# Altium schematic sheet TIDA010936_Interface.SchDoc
size 431 x 279 mm; Date: Not shown in title block; ApprovedBy: Not shown in title block; CheckedBy: Not shown in title block; Author: Not shown in title block; CompanyName: Not shown in title block; Engineer: Not shown in title block; Organization: Not shown in title block; Address1: Not shown in title block; Address2: Not shown in title block; Address3: Not shown in title block; Address4: Not shown in title block; DocumentNumber: 2; Revision: Use project parameter SCH_Rev; SheetNumber: 2; SheetTotal: 3; PageSetup: Record=PageOptions¦CenterHorizontal=True¦CenterVertical=True¦PrintScale=1.00¦XCorrection=1.00¦YCorrection=1.00¦PrintKind=0¦BorderSize=5000000¦LeftOffset=0¦BottomOffset=0¦Orientation=2¦PaperLength=1000¦PaperWidth=1000¦Scale=100¦PaperSource=15¦PrintQuality=600¦MediaType=1¦DitherType=10¦PaperKind=Letter¦PrintScaleMode=1
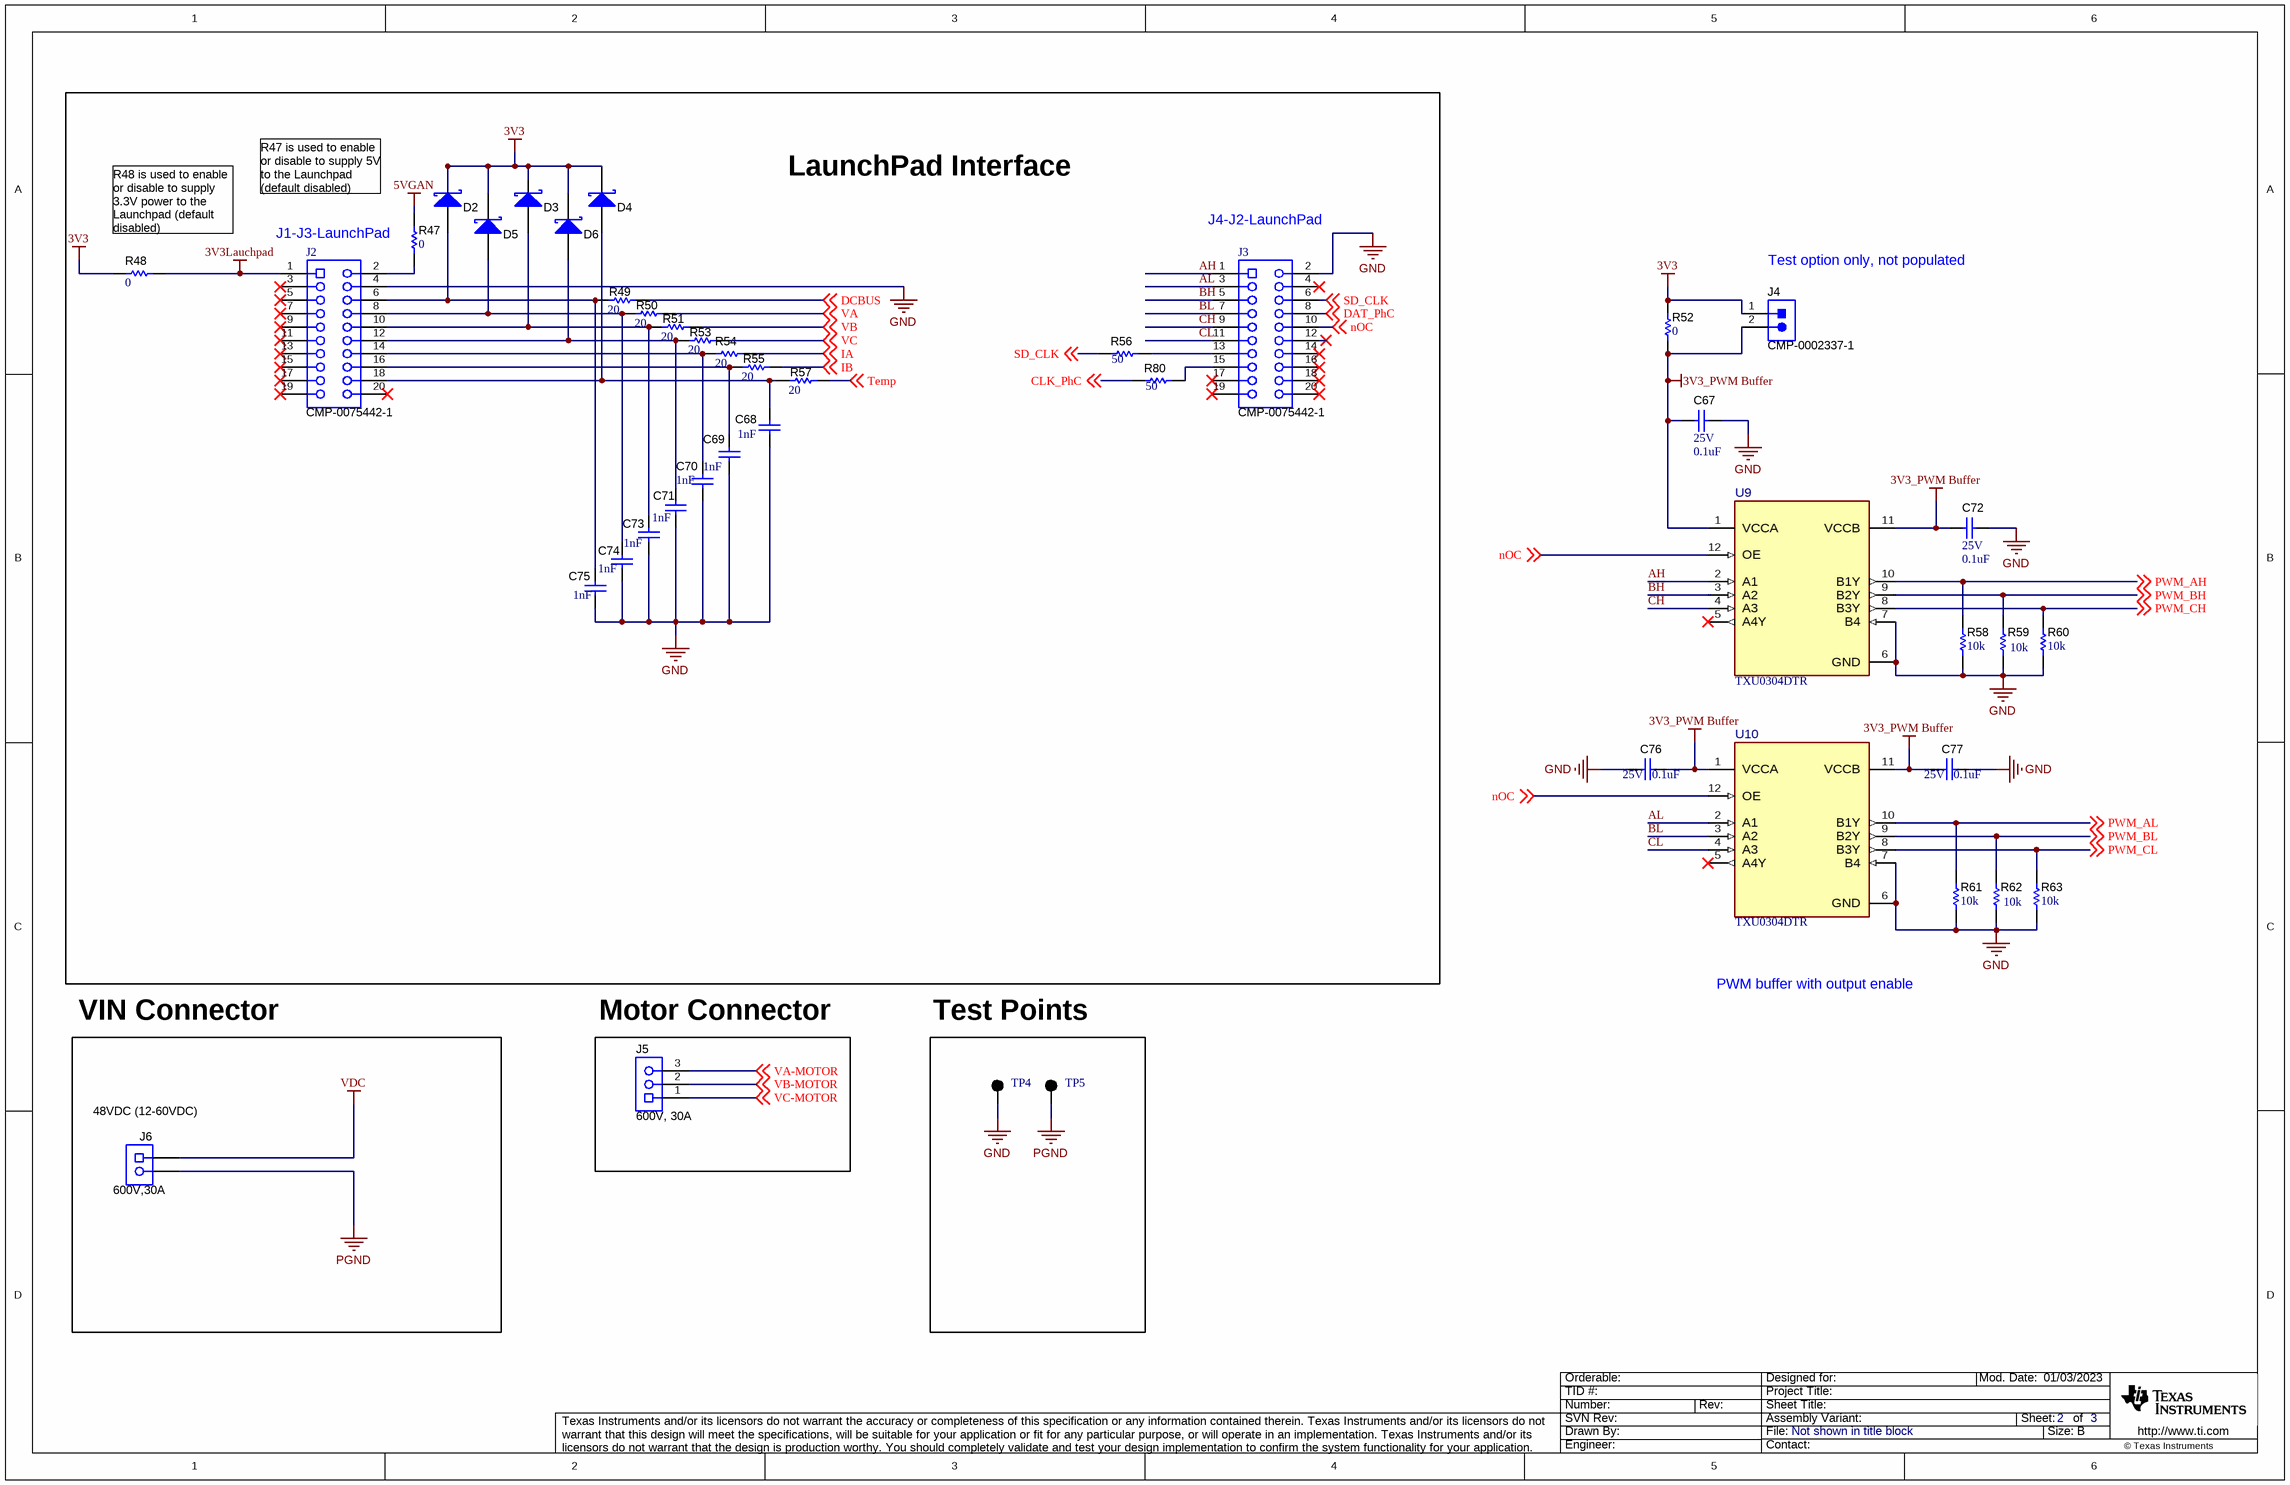
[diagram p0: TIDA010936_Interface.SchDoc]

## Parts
C67  VDC_V: 25V  ValueDisplayed: 0.1uF  [0402]  (hidden comment: GRM155R71E104KE14D)
C68  Cap_F: 1nF  [0603]  (hidden comment: 06031C102JAT2A)
C69  Cap_F: 1nF  [0603]  (hidden comment: 06031C102JAT2A)
C70  Cap_F: 1nF  [0603]  (hidden comment: 06031C102JAT2A)
C71  Cap_F: 1nF  [0603]  (hidden comment: 06031C102JAT2A)
C72  VDC_V: 25V  ValueDisplayed: 0.1uF  [0402]  (hidden comment: GRM155R71E104KE14D)
C73  Cap_F: 1nF  [0603]  (hidden comment: 06031C102JAT2A)
C74  Cap_F: 1nF  [0603]  (hidden comment: 06031C102JAT2A)
C75  Cap_F: 1nF  [0603]  (hidden comment: 06031C102JAT2A)
C76  VDC_V: 25V  ValueDisplayed: 0.1uF  [0402]  (hidden comment: GRM155R71E104KE14D)
C77  VDC_V: 25V  ValueDisplayed: 0.1uF  [0402]  (hidden comment: GRM155R71E104KE14D)
D2  CMP-0028644-3  [SOD-523]  (value not drawn)
D3  CMP-0028644-3  [SOD-523]  (value not drawn)
D4  CMP-0028644-3  [SOD-523]  (value not drawn)
D5  CMP-0028644-3  [SOD-523]  (value not drawn)
D6  CMP-0028644-3  [SOD-523]  (value not drawn)
J2  CMP-0075442-1  [CONN_SSW-110-23-F-D]
J3  CMP-0075442-1  [CONN_SSW-110-23-F-D]
J4  CMP-0002337-1  [CONN_PEC02SAAN]
J5  600V, 30A  [Phoenix_1904150]
J6  600V,30A  [Phoenix_1902547]
R47  ValueDisplayed: 0  [0603]  (hidden comment: PMR03EZPJ000)
R48  ValueDisplayed: 0  [0603]  (hidden comment: PMR03EZPJ000)
R49  ValueDisplayed: 20  [0402]  (hidden comment: CMP-0026876-3)
R50  ValueDisplayed: 20  [0402]  (hidden comment: CMP-0026876-3)
R51  ValueDisplayed: 20  [0402]  (hidden comment: CMP-0026876-3)
R52  ValueDisplayed: 0  [0402]  (hidden comment: CMP-0026822-3)
R53  ValueDisplayed: 20  [0402]  (hidden comment: CMP-0026876-3)
R54  ValueDisplayed: 20  [0402]  (hidden comment: CMP-0026876-3)
R55  ValueDisplayed: 20  [0402]  (hidden comment: CMP-0026876-3)
R56  ValueDisplayed: 50  [0603]  (hidden comment: CRCW060350R0FKEA)
R57  ValueDisplayed: 20  [0402]  (hidden comment: CMP-0026876-3)
R58  ValueDisplayed: 10k  [0402]  (hidden comment: CMP-0026825-5)
R59  ValueDisplayed: 10k  [0402]  (hidden comment: CMP-0026825-5)
R60  ValueDisplayed: 10k  [0402]  (hidden comment: CMP-0026825-5)
R61  ValueDisplayed: 10k  [0402]  (hidden comment: CMP-0026825-5)
R62  ValueDisplayed: 10k  [0402]  (hidden comment: CMP-0026825-5)
R63  ValueDisplayed: 10k  [0402]  (hidden comment: CMP-0026825-5)
R80  ValueDisplayed: 50  [0603]  (hidden comment: CRCW060350R0FKEA)
TP4  CMP-0055138-2  [Keystone5001]  (value not drawn)
TP5  CMP-0055138-2  [Keystone5001]  (value not drawn)
U9  TXU0304DTR  [DTR0012A-MFG]
U10  TXU0304DTR  [DTR0012A-MFG]

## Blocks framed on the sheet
LaunchPad Interface: C68-C71 C73-C75 D2-D6 J2 J3 R47-R51 R53-R57 R80
48VDC (12-60VDC): J6

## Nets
3V3: D2.1(K) D3.1(K) D4.1(K) D5.1(K) D6.1(K) J4.1 R48.2 R52.2
3V3_PWM Buffer: C67.1 C72.1 C76.2 C77.1 J4.2 R52.1 U9.1(VCCA) U9.11(VCCB) U10.1(VCCA) U10.11(VCCB)
3V3Lauchpad: J2.1 R48.1
5VGAN: R47.1
GND: C67.2 C68.2 C69.2 C70.2 C71.2 C72.2 C73.2 C74.2 C75.2 C76.1 C77.2 J2.4 J3.2 R58.1 R59.1 R60.1 R61.1 R62.1 R63.1 TP4.1 U9.6(GND) U9.7(B4) U10.6(GND) U10.7(B4)
PGND: J6.2 TP5.1
VDC: J6.1
AH: J3.1 U9.2(A1)
AL: J3.3 U10.2(A1)
BH: J3.5 U9.3(A2)
BL: J3.7 U10.3(A2)
CH: J3.9 U9.4(A3)
CL: J3.11 U10.4(A3)
CLK_PhC: R80.1 ; off-sheet CLK_PhC
DAT_PhC: J3.8 ; off-sheet DAT_PhC
DCBUS: R49.1 ; off-sheet DCBUS
IA: R54.1 ; off-sheet IA
IB: R55.1 ; off-sheet IB
nOC: J3.10 U9.12(OE) U10.12(OE) ; off-sheet nOC
PWM_AH: R58.2 U9.10(B1Y) ; off-sheet PWM_AH
PWM_AL: R61.2 U10.10(B1Y) ; off-sheet PWM_AL
PWM_BH: R59.2 U9.9(B2Y) ; off-sheet PWM_BH
PWM_BL: R62.2 U10.9(B2Y) ; off-sheet PWM_BL
PWM_CH: R60.2 U9.8(B3Y) ; off-sheet PWM_CH
PWM_CL: R63.2 U10.8(B3Y) ; off-sheet PWM_CL
SD_CLK: J3.6 R56.1 ; off-sheet SD_CLK
Temp: R57.1 ; off-sheet Temp
VA: R50.1 ; off-sheet VA
VA-MOTOR: J5.3 ; off-sheet VA-MOTOR
VB: R51.1 ; off-sheet VB
VB-MOTOR: J5.2 ; off-sheet VB-MOTOR
VC: R53.1 ; off-sheet VC
VC-MOTOR: J5.1 ; off-sheet VC-MOTOR
NetC68_1: C68.1 D4.2(A) J2.18 R57.2
NetC69_1: C69.1 J2.16 R55.2
NetC70_1: C70.1 J2.14 R54.2
NetC71_1: C71.1 D6.2(A) J2.12 R53.2
NetC73_1: C73.1 D3.2(A) J2.10 R51.2
NetC74_1: C74.1 D5.2(A) J2.8 R50.2
NetC75_1: C75.1 D2.2(A) J2.6 R49.2
NetJ2_2: J2.2 R47.2
NetJ3_13: J3.13 R56.2
NetJ3_15: J3.15 R80.2

Not connected (* = marked no-connect by the designer): J2 3* 5* 7* 9* 11* 13* 15* 17* 19* 20*; J3 4* 12* 14* 16* 17* 18* 19* 20*; U9 5(A4Y)*; U10 5(A4Y)*

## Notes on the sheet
- (near R48) R48 is used to enable or disable to supply 3.3V power to the Launchpad (default disabled)
- R47 is used to enable or disable to supply 5V to the Launchpad (default disabled)
- J1-J3-LaunchPad
- (near J3) J4-J2-LaunchPad
- (near J4) Test option only, not populated
- VIN Connector
- (near J5) Motor Connector
- Test Points
- PWM buffer with output enable

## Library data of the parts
C67 C72 C76 C77 = CMP-0006659-2: CAP, CERM, 0.1 uF, 25 V, +/- 10%, X7R, 0402; Manufacturer: MuRata; TaMin_C: -55°C; Polarized: N; SizeAreaWB_mm2: 3; Value1: Unknown; U/M: EA; Value: 0.1uF; TaMax_C: 125°C; SizeZ_mm: 0.6; SizeX_mm: 1; SizeY_mm: 0.5; Cap_F: 100nF; AEC Category: Q200
C68-C71 C73-C75 = CMP-0006723-2: CAP, CERM, 1000 pF, 100 V, +/- 5%, X7R, 0603; Manufacturer: AVX; TaMin_C: -55°C; ESR_ohm: 0.276; Polarized: N; SizeAreaWB_mm2: 4.68; Value1: 0.276 ohm; U/M: EA; Value: 1000pF; TaMax_C: 125°C; SizeZ_mm: 1; SizeX_mm: 1.6; SizeY_mm: 0.8; Value2: 100V; SizeArea_mm2: 1.28; AEC Category: Q200
D2-D6 = CMP-0028644-3: Diode, Schottky, 70 V, 0.07 A, SOD-523; PartNumber: 1PS79SB70,115; Manufacturer: Nexperia; Vf_V: 410mV; Value: 70V; Value1: 0.07A; Value2: 0.41V; Io_A: 70mA; TJmax_C: 150°C; SizeAreaWB_mm2: 5.13; SizeArea_mm2: 1.53; SizeX_mm: 1.7; SizeY_mm: 0.9; SizeZ_mm: 0.65; AEC Category: Q101; Green_Lifecycle: Not Set; Green_REACh: Incomplete
J2 J3 = CMP-0075442-1: Connector, Receptacle, 100mil, 10x2, Gold plated, TH; PartNumber: SSW-110-23-F-D; Manufacturer: Samtec; CompType: Socket Strip; Green_Lifecycle: Active; Green_REACh: Passed; CT: True; CNHeader: False
J4 = CMP-0002337-1: Header, 100mil, 2x1, Tin, TH; PartNumber: PEC02SAAN; Manufacturer: Sullins Connector Solutions; Pitch_mm: 2.54; Gender: Male; Shrouded: N; Row_Count: 1; Current_A: 3A; Voltage_V: 1.8kV; Cert_UL: Y; CNHeader: TRUE; Green_Lifecycle: Not Set; Green_REACh: Incomplete; CT: FALSE
J5 = CMP-0055528-1: Terminal Block, 9.52mm, 3x1, R/A, TH; Manufacturer: Phoenix Contact; PartNumber: 1904150; Cert_VDE: Y; CNHeader: FALSE; Current_A: 32A; Gender: Female; Voltage_V: 1kV; Row_Count: 1; Pitch_mm: 9.52; CT: TRUE
J6 = CMP-0055527-1: Terminal Block, 9.52mm, 2x1, R/A, TH; PartNumber: 1902547; Manufacturer: Phoenix Contact; Pitch_mm: 9.52; Gender: Female; Row_Count: 1; Current_A: 32A; Voltage_V: 1kV; Cert_UL: Y; CNHeader: FALSE; CT: TRUE
R47 R48 = CMP-0086358-1: RES, 0, 0%, 0.25 W, AEC-Q200 Grade 0, 0603; Manufacturer: Rohm; Power_W: 250mW; SizeZ_mm: 1; SizeArea_mm2: 1.28; Value2: 0.25W; SizeAreaWB_mm2: 4.68; Value_Code: 0000; Value: 0; AEC Qualified: Y; AEC Category: Q200; SizeX_mm: 1.6; SizeY_mm: 0.8
R49-R51 R53-R55 R57 = CMP-0026876-3: RES, 20, 5%, 0.063 W, AEC-Q200 Grade 0, 0402; PartNumber: CRCW040220R0JNED; Manufacturer: Vishay-Dale; Value: 20; Value_Code: 20R0; Power_W: 63mW; Value2: 0.063W; VDC_V: 50V; TempCo: 200 ppm/C; EIA_Code: E24; AEC Category: Q200; AEC Qualified: Y; AEC Grade: 0; SizeArea_mm2: 0.5; SizeX_mm: 1; SizeZ_mm: 0.6
R52 = CMP-0026822-3: RES, 0, 5%, 0.063 W, AEC-Q200 Grade 0, 0402; PartNumber: CRCW04020000Z0ED; Manufacturer: Vishay-Dale; Value: 0; Value_Code: 0000; Power_W: 63mW; Value2: 0.063W; VDC_V: 50V; TempCo: 200 ppm/C; SizeArea_mm2: 0.5; SizeX_mm: 1; SizeZ_mm: 0.6; EIA_Code: E24; AEC Category: Q200; AEC Qualified: Y
R56 R80 = CMP-0022479-4: RES, 50, 1%, 0.1 W, AEC-Q200 Grade 0, 0603; Manufacturer: Vishay-Dale; Power_W: 100mW; TempCo: 100 ppm/C; Value_Code: 50R0; Value: 50; SizeX_mm: 1.6; SizeY_mm: 0.8; SizeZ_mm: 1; Value2: 0.1W; SizeArea_mm2: 1.28; AEC Qualified: Y; VDC_V: 75V; AEC Category: Q200; AEC Grade: 0
R58-R63 = CMP-0026825-5: RES, 10 k, 5%, 0.063 W, AEC-Q200 Grade 0, 0402; PartNumber: CRCW040210K0JNED; Manufacturer: Vishay-Dale; Value: 10k; Value_Code: 10k0; Power_W: 63mW; Value2: 0.063W; VDC_V: 50V; TempCo: 200 ppm/C; SizeArea_mm2: 0.5; SizeX_mm: 1; SizeZ_mm: 0.6; EIA_Code: E24; AEC Category: Q200; AEC Qualified: Y; AEC Grade: 0
TP4 TP5 = CMP-0055138-2: Test Point, Miniature, Black, TH; Manufacturer: Keystone Electronics; ContactFinish: Silver; CNHeader: FALSE; Green_Lifecycle: Active; Green_REACh: Passed; CT: TRUE
U9 U10 = CMP-0091905-2: 4-Bit Fixed Direction Voltage-Level Translator with SchmittTrigger Inputs, and Tri-State Outputs; Manufacturer: Texas Instruments; AEC Category: Q200; Number Of Outputs: 4; PositionCount: 1; V B Min: 1.1V; V A Max: 5.5V; CompType: IC; SizeZ_mm: 0.4mm; Standoff Height: 0mm; Logic Function Desc: Non-Inverting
